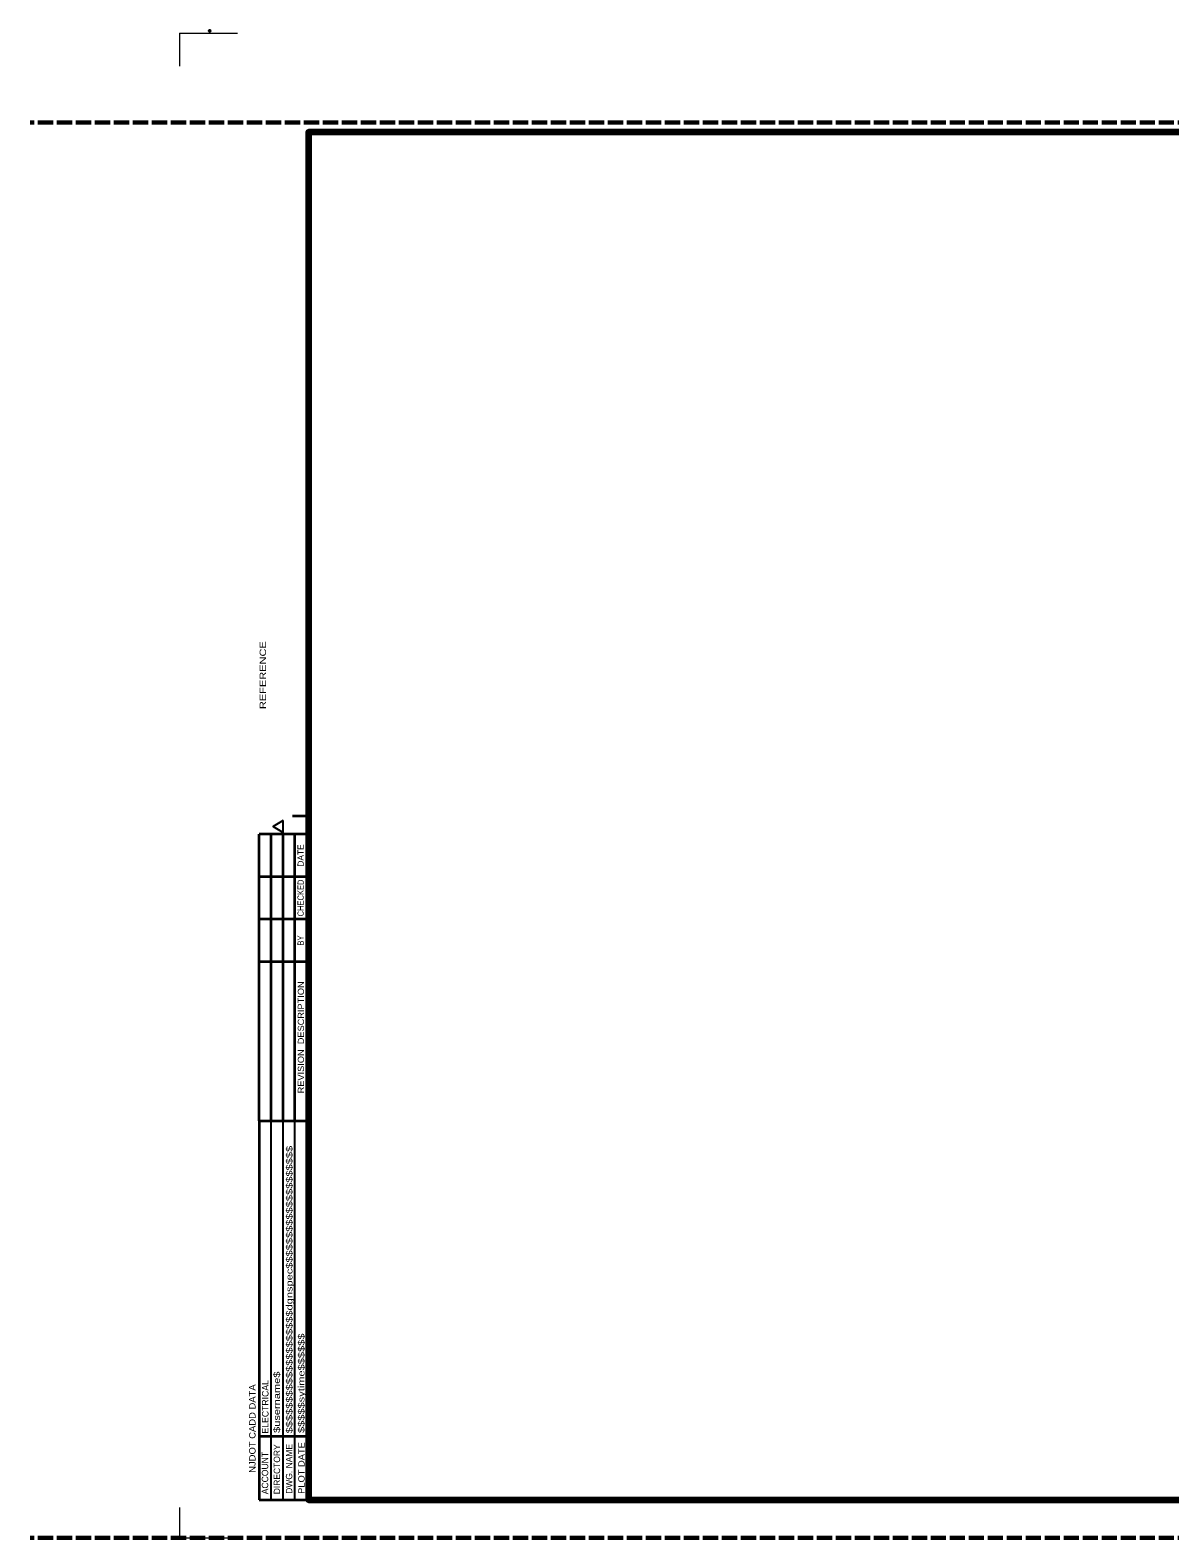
# Model space of a CAD drawing. Extents: x 214965 to 215235, y 214718 to 214897.
# Drawn here: x 214965 to 215100, y 214718.8 to 214897.4 of the extents above; entities that cross this region are included whole.
import ezdxf
from ezdxf.enums import TextEntityAlignment as Align

# ---------------------------------------------------------------- set-up
doc = ezdxf.new("R2010")
doc.units = 0
doc.header["$LTSCALE"] = 0.3
doc.header["$PDMODE"] = 32
doc.header["$PDSIZE"] = 0.15
doc.linetypes.add('LONG_DASHED', pattern=[7.5, 6, -1.5])
doc.layers.add('1', color=7, linetype='Continuous', lineweight=35)
doc.layers.add('25', color=7, linetype='Continuous', lineweight=35)

msp = doc.modelspace()

# ---------------------------------------------------------------- linework, layer by layer
at = {"layer": '1', "lineweight": 13}
for p, q in [((214982.6614, 214897.0062), (214982.6614, 214893.1062)), ((214982.6614, 214897.0062), (214989.5614, 214897.0062)), ((214982.6614, 214722.4062), (214982.6614, 214718.8062)), ((214982.6614, 214718.8062), (214989.5614, 214718.8062))]:
    msp.add_line(p, q, dxfattribs=at)
at = {"layer": '1', "linetype": 'LONG_DASHED', "lineweight": 60}
for p, q in [((215233.2114, 214886.4462), (214964.9874, 214886.4462)), ((215233.2114, 214718.8062), (214964.9874, 214718.8062))]:
    msp.add_line(p, q, dxfattribs=at)
at = {"layer": '1'}
for p, q in [((214996.0414, 214804.3062), (214997.9614, 214804.3062)), ((214992.1241, 214768.1977), (214997.9614, 214768.1977)), ((214992.1241, 214768.1977), (214992.1241, 214723.3062)), ((214992.1241, 214730.8423), (214997.9614, 214730.8423)), ((214992.1241, 214723.3062), (214997.9614, 214723.3062))]:
    msp.add_line(p, q, dxfattribs=at)
at = {"layer": '1', "lineweight": 25}
for p, q in [((214993.5427, 214723.3062), (214993.5427, 214768.1977)), ((214994.9614, 214723.3062), (214994.9614, 214768.1977)), ((214996.3439, 214723.3062), (214996.3439, 214768.1977))]:
    msp.add_line(p, q, dxfattribs=at)
at = {"layer": '1', "lineweight": 158}
msp.add_lwpolyline([(215230.4614, 214723.3062), (215230.4614, 214885.3062), (214997.9614, 214885.3062), (214997.9614, 214723.3062)], close=True, dxfattribs=at)
at = {"layer": '1'}
msp.add_point((214986.2614, 214897.3062), dxfattribs=at)
at = {"layer": '25'}
for p, q in [((214997.9614, 214802.1375), (214992.1241, 214802.1375)), ((214992.1241, 214768.1977), (214992.1241, 214802.1375)), ((214993.5427, 214768.1977), (214993.5427, 214802.1375)), ((214994.9614, 214768.1977), (214994.9614, 214802.1375)), ((214996.3439, 214768.1977), (214996.3439, 214802.1375)), ((214997.9614, 214797.1044), (214992.1241, 214797.1044)), ((214997.9614, 214792.0712), (214992.1241, 214792.0712)), ((214997.9614, 214787.0381), (214992.1241, 214787.0381)), ((214997.7626, 214787.0381), (214996.3439, 214787.0381))]:
    msp.add_line(p, q, dxfattribs=at)
at = {"layer": '25', "lineweight": 25}
msp.add_lwpolyline([(214994.9704, 214803.764), (214993.7506, 214803.0592), (214994.9704, 214802.3544)], close=True, dxfattribs=at)

# ---------------------------------------------------------------- texts
at = {"layer": '1'}
for s, height, width, p in [('REFERENCE                                                              ', 0.75, 1.3, (214992.9214, 214816.9662)), ('$$$$$$$$$$$$$$$$$$$$dgnspec$$$$$$$$$$$$$$$$$$$$', 0.7526, 1.3, (214996.0548, 214731.1857)), ('$$$$$sytime$$$$$$', 0.7526, 1.3, (214997.4734, 214731.2219)), ('$username$', 0.7526, 1.3, (214994.5728, 214731.2309)), ('NJDOT CADD DATA', 0.759, 1.1, (214991.6813, 214726.505)), ('PLOT DATE', 0.7499, 1.1, (214997.4915, 214724.011))]:
    msp.add_text(s, height=height, rotation=90, dxfattribs=dict(at, width=width)).set_placement(p)
for s, height, p in [('ELECTRICAL', 0.768, (214993.2174, 214731.1586)), ('DIRECTORY', 0.75, (214994.5909, 214723.9749)), ('DWG. NAME', 0.75, (214996.0277, 214724.0201)), ('ACCOUNT', 0.7589, (214993.1813, 214723.9658))]:
    msp.add_text(s, height=height, rotation=90, dxfattribs=at).set_placement(p)
at = {"layer": '25'}
msp.add_text('DATE', height=0.741, rotation=90, dxfattribs=at).set_placement((214997.3921, 214799.6275), align=Align.CENTER)
for s, width, p in [('CHECKED', 0.9, (214997.3921, 214794.5937)), ('BY', 0.9, (214997.3921, 214789.5572)), ('REVISION  DESCRIPTION', 1.1, (214997.4283, 214778.0864))]:
    msp.add_text(s, height=0.741, rotation=90, dxfattribs=dict(at, width=width)).set_placement(p, align=Align.CENTER)

doc.saveas('drawing.dxf')
